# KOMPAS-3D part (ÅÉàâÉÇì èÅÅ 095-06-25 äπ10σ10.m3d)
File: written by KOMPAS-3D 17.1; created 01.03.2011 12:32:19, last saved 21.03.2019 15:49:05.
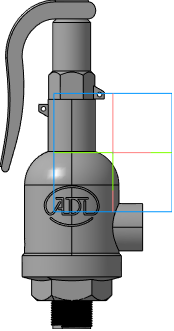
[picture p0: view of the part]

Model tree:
1. Операция без истории:1

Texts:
  Viktor2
